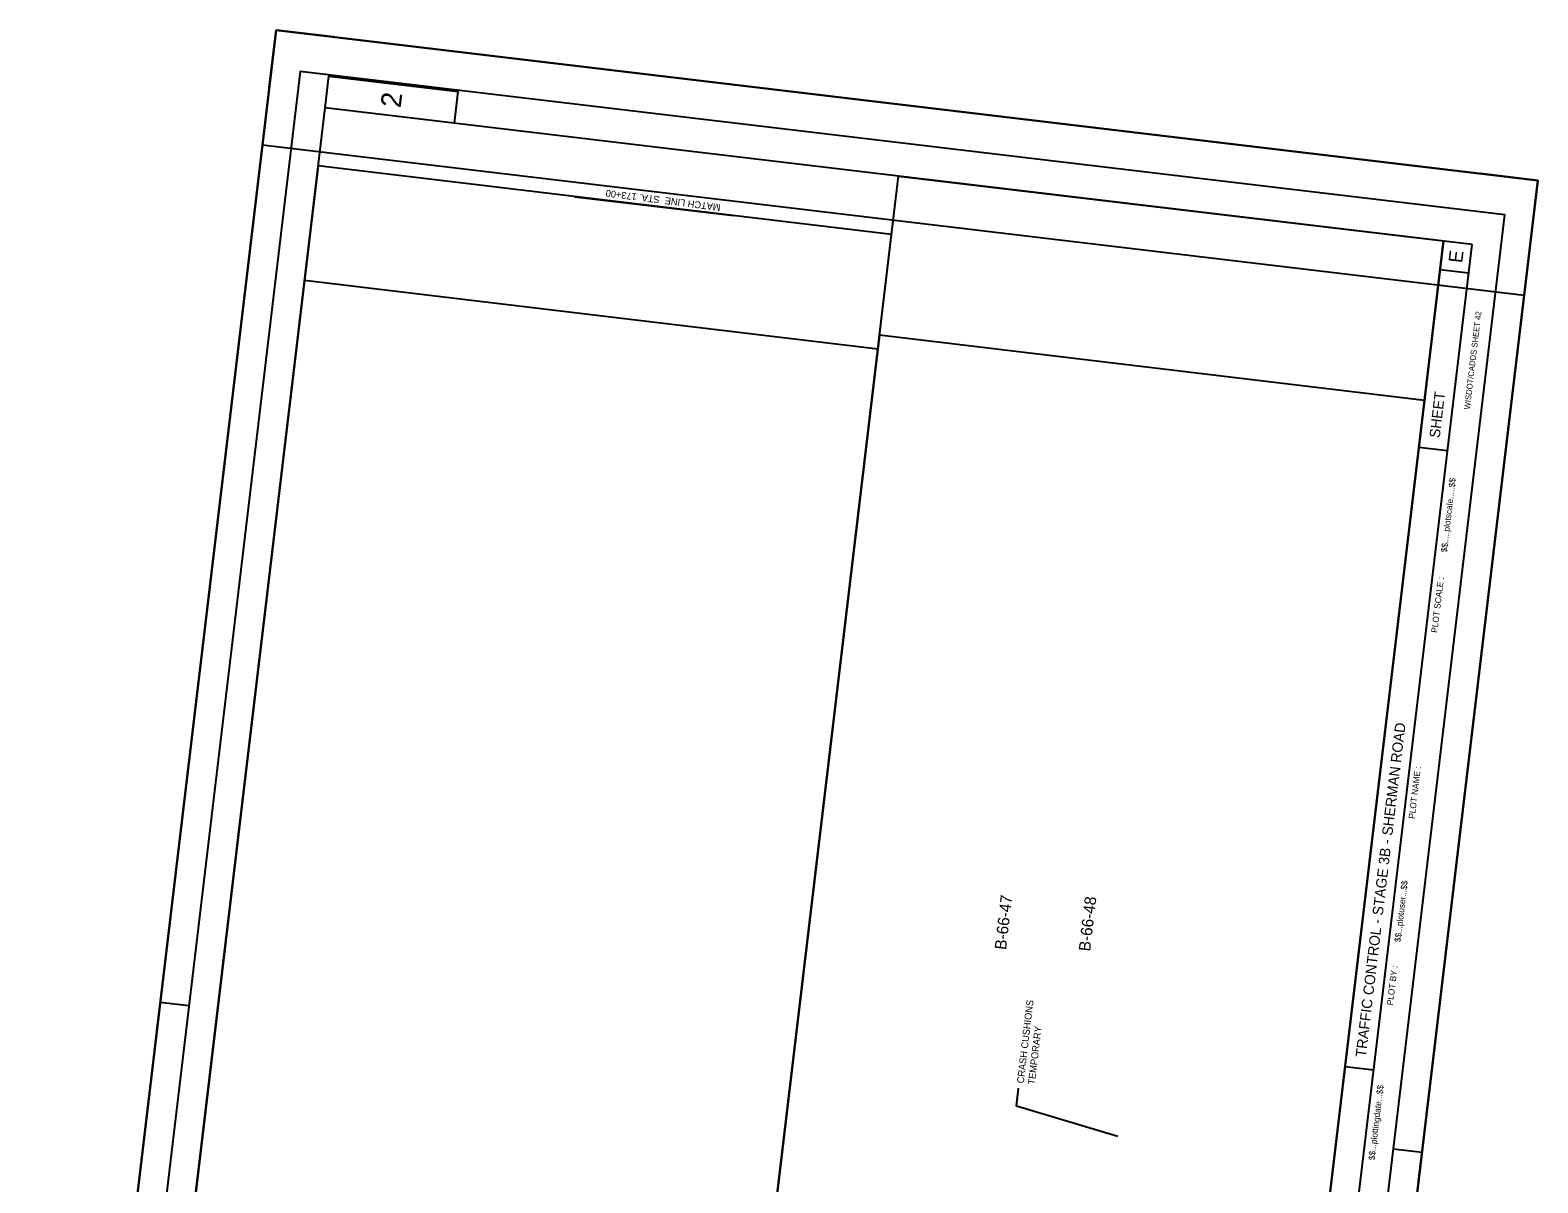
# Model space of a CAD drawing. Extents: x 361130 to 362436, y 140169 to 142087.
# Drawn here: x 361130 to 362436, y 141089 to 142087 of the extents above; entities that cross this region are included whole.
import ezdxf

# ---------------------------------------------------------------- set-up
doc = ezdxf.new("R2010")
doc.units = 0
for name, color, linetype in [('Default', 7, 'Continuous'), ('P_ALI_20', 7, 'Continuous'), ('P_ALI_200_Sta', 7, 'Continuous'), ('P_ALI_20_PIData', 7, 'Continuous'), ('P_ALI_20_Sta', 7, 'Continuous'), ('P_ALI_20_Tic', 7, 'Continuous'), ('P_ALI_50_Equation', 7, 'Continuous'), ('P_ALI_50_PIData', 7, 'Continuous'), ('P_ALI_50_Tic', 7, 'Continuous')]:
    doc.layers.add(name, color=color, linetype=linetype)

msp = doc.modelspace()

# ---------------------------------------------------------------- linework, layer by layer
msp.add_lwpolyline([(361130.4, 140299.5), (361331.5, 141987.6), (362423.8, 141857.5), (362222.7, 140169.4), (361130.4, 140299.5)])
at = {"layer": 'Default'}
for points in [[(361190.4, 140380.5), (361686.9, 140321), (361864.3, 141810.6), (361367.8, 141870.1)], [(361190.4, 140380.5), (361686.9, 140321), (361864.3, 141810.6), (361367.8, 141870.1)], [(361190.4, 140380.5), (361686.9, 140321), (361864.3, 141810.6), (361367.8, 141870.1)], [(361688.3, 140333.4), (362160, 140276.9), (362337.4, 141766.3), (361865.7, 141822.8)], [(361688.3, 140333.4), (362160, 140276.9), (362337.4, 141766.3), (361865.7, 141822.8)], [(361688.3, 140333.4), (362160, 140276.9), (362337.4, 141766.3), (361865.7, 141822.8)]]:
    msp.add_lwpolyline(points, close=True, dxfattribs=at)
at = {"layer": 'P_ALI_20'}
for p, q in [((361337.4, 142037.3), (361343.3, 142086.9)), ((361393, 142081), (361343.3, 142086.9)), ((361199.4, 140455.7), (361385.7, 142019.7)), ((362378.7, 141901.4), (361385.7, 142019.7)), ((361695.9, 140396.6), (361882.2, 141960.5)), ((362435.6, 141956.8), (362386, 141962.7)), ((362429.7, 141907.2), (362435.6, 141956.8)), ((362167.5, 140340.4), (362353.8, 141904.4)), ((362192.4, 140337.5), (362378.7, 141901.4)), ((362375.7, 141876.6), (362350.9, 141879.5)), ((362357.4, 141722.7), (362332.5, 141725.6)), ((361240.1, 141220.5), (361246, 141270.2)), ((361243.1, 141245.4), (361267.9, 141242.4)), ((362293.5, 141186.5), (362268.7, 141189.4)), ((362332.4, 141090.4), (362338.3, 141140.1)), ((362335.4, 141115.3), (362310.5, 141118.2))]:
    msp.add_line(p, q, dxfattribs=at)
msp.add_lwpolyline([(361385.7, 142019.7), (361388.9, 142047), (361500.6, 142033.7), (361497.4, 142006.4)], close=True, dxfattribs=at)
at = {"layer": 'P_ALI_200_Sta'}
msp.add_line((361684, 140297.3), (361870.3, 141861.2), dxfattribs=at)
at = {"layer": 'P_ALI_20_PIData'}
for points in [[(361438.2, 140859.9), (361387.4, 140433.3), (361695.9, 140396.6), (361746.9, 140825.3), (361876.1, 141909.9), (361379.7, 141969.4), (361250.2, 140882.3)], [(362093.1, 140388), (362016.4, 140394.8), (361700.3, 140433.8), (361882.2, 141960.5), (362353.8, 141904.4), (362214.8, 140737.4), (362136.1, 140746.7)]]:
    msp.add_lwpolyline(points, close=True, dxfattribs=at)
at = {"layer": 'P_ALI_20_Sta'}
msp.add_lwpolyline([(362072.1, 141129.2), (361984.2, 141155.3), (361986, 141170.8)], dxfattribs=at)
at = {"layer": 'P_ALI_20_Tic'}
msp.add_lwpolyline([(361142.3, 140398.8), (361343.3, 142086.9), (362435.6, 141956.8), (362234.5, 140268.7)], close=True, dxfattribs=at)
at = {"layer": 'P_ALI_50_Equation'}
msp.add_line((361602, 141942.7), (361739.2, 141926.3), dxfattribs=at)
at = {"layer": 'P_ALI_50_Tic'}
for points in [[(362234.5, 140268.7), (362435.6, 141956.8), (361343.3, 142086.9), (361142.3, 140398.8)], [(362211.1, 140283.6), (362406.9, 141927), (361364.2, 142051.2), (361168.5, 140407.8)]]:
    msp.add_lwpolyline(points, close=True, dxfattribs=at)

# ---------------------------------------------------------------- texts
at = {"layer": 'P_ALI_20'}
for s, height, rotation, p in [('2', 17.5, 83.2076, (361451.1, 142019.1)), ('E', 12, 83.2076, (362370.1, 141884.9)), ('WISDOT/CADDS SHEET 42', 5, 83.2076, (362376.7, 141758.3)), ('SHEET ', 9, 83.2076, (362350.6, 141733.5)), ('$$.....plotscale.....$$', 5.4, 83.2076, (362356.9, 141634.6)), ('PLOT SCALE : ', 5.4, 83.2076, (362348.6, 141564.9)), ('TRAFFIC CONTROL - STAGE 3B - SHERMAN ROAD', 9, 83.2076, (362286.7, 141197.3)), ('PLOT NAME :                      ', 5.4, 83.2076, (362329, 141403.8)), ('$$...plotuser...$$', 5.4, 83.2075, (362316.7, 141297)), ('PLOT BY :', 5.4, 83.2075, (362310.2, 141242.4)), ('$$...plottingdate...$$', 5.4, 83.2075, (362294.3, 141108.3))]:
    msp.add_text(s, height=height, rotation=rotation, dxfattribs=at).set_placement(p)
at = {"layer": 'P_ALI_20_Sta'}
for s, height, rotation, p in [('B-66-47', 10, 83.3336, (361975.2, 141290.3)), ('B-66-48', 10, 83.3336, (362048, 141289)), ('CRASH CUSHIONS', 6, 83.2076, (361990.5, 141174.8)), ('TEMPORARY', 6, 83.2076, (362000.1, 141173.7))]:
    msp.add_text(s, height=height, rotation=rotation, dxfattribs=at).set_placement(p)
at = {"layer": 'P_ALI_50_PIData'}
msp.add_text('MATCH LINE  STA. 173+00', height=6, rotation=172.7522, dxfattribs=at).set_placement((361728.4, 141936.2))

doc.saveas('drawing.dxf')
